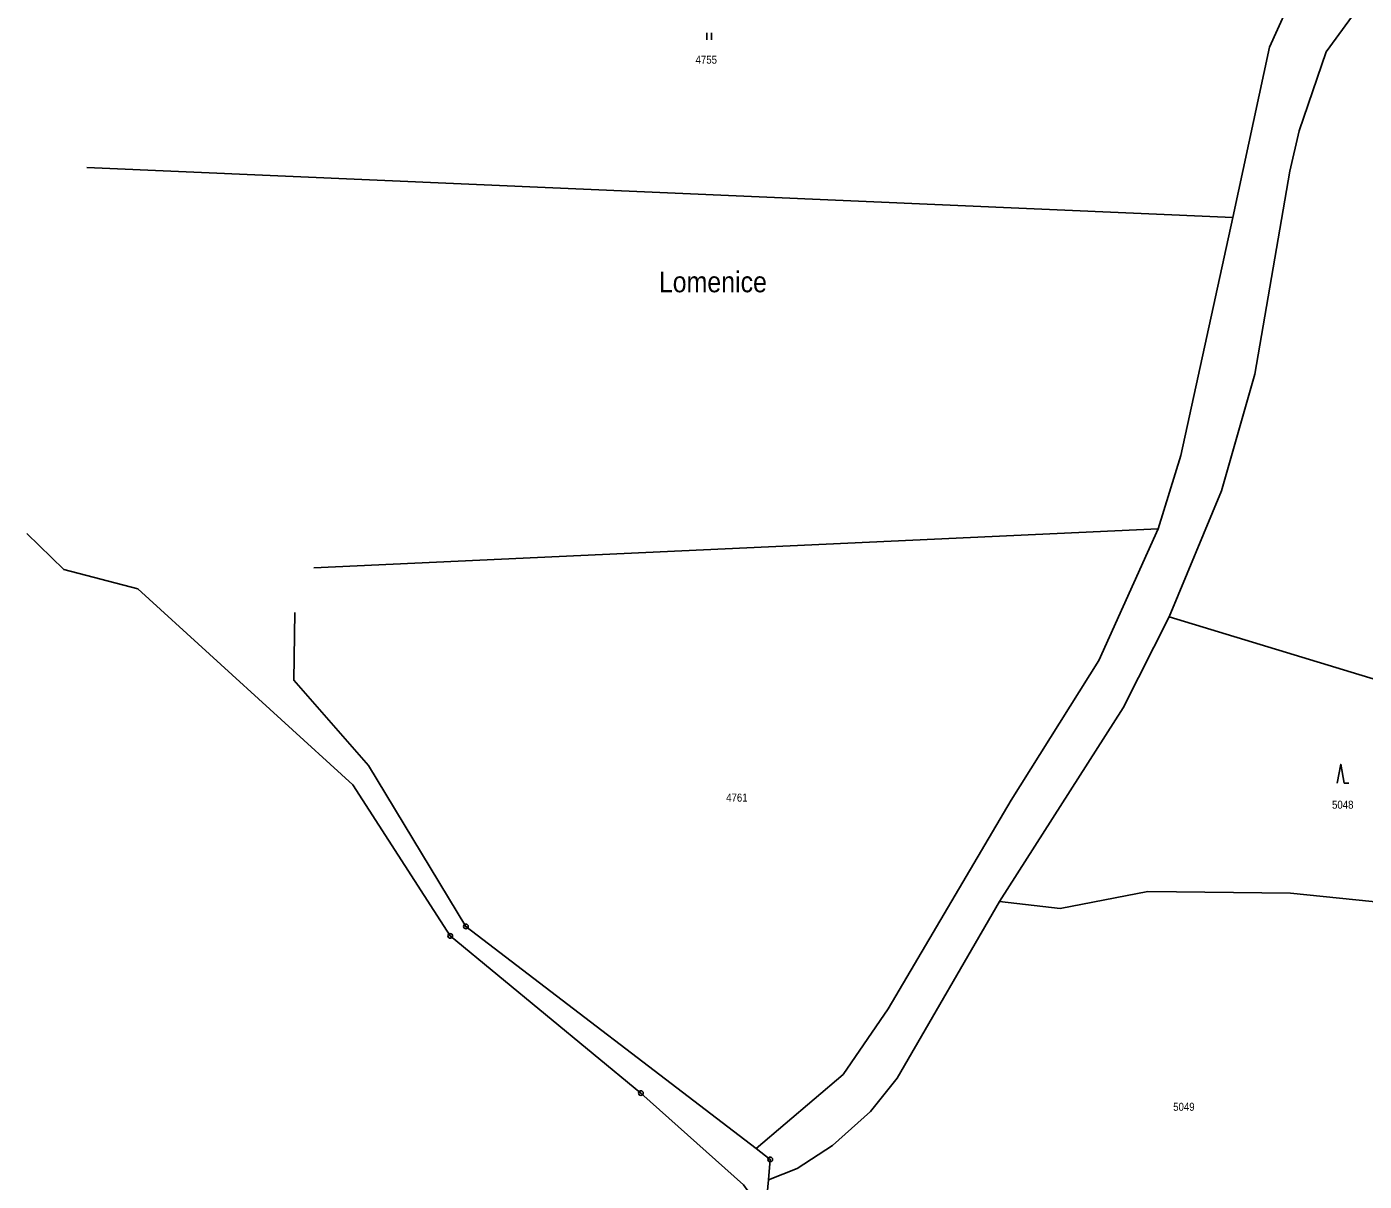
# Model space of a CAD drawing. Extents: x -665688 to -664583, y -1006118 to -1004927.
# Drawn here: x -665688.4 to -665404.3, y -1005890.9 to -1005645.6 of the extents above; entities that cross this region are included whole.
import ezdxf
from ezdxf.enums import TextEntityAlignment as Align

# ---------------------------------------------------------------- set-up
doc = ezdxf.new("R2010")
doc.units = 0
doc.header["$LTSCALE"] = 0.68
for name, color, linetype, lineweight in [('1', 7, 'Continuous', 25), ('24', 7, 'Continuous', 25), ('25', 7, 'Continuous', 25)]:
    doc.layers.add(name, color=color, linetype=linetype, lineweight=lineweight)
doc.layers.add('15', color=7, linetype='Continuous')
doc.layers.add('18', color=7, linetype='Continuous')

msp = doc.modelspace()

# ---------------------------------------------------------------- linework, layer by layer
at = {"layer": '1'}
msp.add_line((-665627.42, -1005760.59), (-665448.03, -1005752.29), dxfattribs=at)
for points in [[(-665445.72, -1005770.98), (-665434.59, -1005744.22), (-665427.51, -1005719.43), (-665420.06, -1005676.31), (-665418.1, -1005667.75), (-665412.35, -1005650.92), (-665401.43, -1005635.84), (-665388.69, -1005628.79), (-665366.67, -1005621.78), (-665309.42, -1005612.82)], [(-665415.62, -1005632.24), (-665418.98, -1005637.81), (-665424.38, -1005649.94), (-665432.19, -1005686.1)], [(-665432.19, -1005686.1), (-665553.92, -1005680.79), (-665675.65, -1005675.48)], [(-665432.19, -1005686.1), (-665443.23, -1005736.68), (-665448.03, -1005752.29)], [(-665323.94, -1005707.89), (-665346.55, -1005715.92), (-665359.1, -1005723.44), (-665368.23, -1005735.3), (-665382.37, -1005776.17), (-665390.96, -1005787.59), (-665445.72, -1005770.98)], [(-665688.38, -1005753.28), (-665680.51, -1005760.89), (-665664.8, -1005765.04), (-665619.09, -1005806.67), (-665598.43, -1005838.79), (-665557.93, -1005872.16), (-665536.17, -1005891.7), (-665531.55, -1005898.07)], [(-665448.03, -1005752.29), (-665460.64, -1005780.25), (-665479.25, -1005809.91), (-665505.4, -1005854.24), (-665515, -1005868.23), (-665533.44, -1005883.98)], [(-665533.44, -1005883.98), (-665595.09, -1005836.76), (-665615.82, -1005802.55), (-665631.65, -1005784.46), (-665631.42, -1005770.03)], [(-665481.79, -1005831.46), (-665455.47, -1005790.3), (-665445.72, -1005770.98)], [(-665481.79, -1005831.46), (-665468.84, -1005832.94), (-665450.28, -1005829.35), (-665419.93, -1005829.7), (-665364.46, -1005835.39)], [(-665530.86, -1005890.61), (-665524.77, -1005888.22), (-665517.25, -1005883.29), (-665509.16, -1005876.07), (-665503.51, -1005869.02), (-665481.79, -1005831.46)], [(-665530.86, -1005890.61), (-665530.46, -1005886.28), (-665533.44, -1005883.98)], [(-665470.32, -1005911.86), (-665490.2, -1005908.29), (-665515.84, -1005902), (-665531.27, -1005895.08), (-665530.86, -1005890.61)]]:
    msp.add_lwpolyline(points, dxfattribs=at)
at = {"layer": '24'}
for centre, radius in [((-665595.09, -1005836.76), 0.5), ((-665595.09, -1005836.76), 0.032), ((-665598.43, -1005838.79), 0.5), ((-665598.43, -1005838.79), 0.032), ((-665557.93, -1005872.16), 0.5), ((-665557.93, -1005872.16), 0.032), ((-665530.46, -1005886.28), 0.5), ((-665530.46, -1005886.28), 0.032)]:
    msp.add_circle(centre, radius, dxfattribs=at)
at = {"layer": '25'}
for p, q in [((-665543.947, -1005648.395), (-665543.947, -1005646.895)), ((-665542.913, -1005648.395), (-665542.913, -1005646.895))]:
    msp.add_line(p, q, dxfattribs=at)
msp.add_lwpolyline([(-665410.04, -1005806.31), (-665409.29, -1005802.31), (-665408.54, -1005806.31), (-665407.54, -1005806.31)], dxfattribs=at)

# ---------------------------------------------------------------- texts
at = {"layer": '15', "width": 0.9}
msp.add_text('Lomenice', height=4.4, dxfattribs=at).set_placement((-665542.64, -1005702.02), align=Align.CENTER)
at = {"layer": '18', "width": 0.9}
for s, p in [('4755', (-665544.0395, -1005653.45)), ('4761', (-665537.5395, -1005810.24)), ('5048', (-665408.8495, -1005811.75)), ('5049', (-665442.5895, -1005875.93))]:
    msp.add_text(s, height=1.7, dxfattribs=at).set_placement(p, align=Align.CENTER)

doc.saveas('drawing.dxf')
